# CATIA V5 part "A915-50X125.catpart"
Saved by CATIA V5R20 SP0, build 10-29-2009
Part number: A915-50X125
Source: Unknown
Property "A": "0.000"
Property "ARTICLENO": "A915-50X125"
Property "BOMINFO": "A915-50X125"
Property "CODE": "A915-50X125"
Property "CREATOR": "CADENAS GmbH"
Property "D": "13.500"
Property "D1": "20.000"
Property "FORM": "B"
Property "L": "125.000"
Property "L1": "25.000"
Property "L2": "75.000"
Property "LINA": "A915-50X125"
Property "NB": "A915-50X125"
Property "NBSYN": "$CODE."
Property "NN": "A915"
Property "NT": "VDI 3357 Wear Plates, steel"
Property "SCREW": "M12x25"
Property "SUPPLIER": "CF"
Property "T": "13.000"
Property "W": "50.000"
Bounding box of the stored display mesh (mm): x 0 to 20, y 0 to 125, z -25 to 25
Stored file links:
  C:\Users\borellobunino\Desktop\3D X SITO CF\A915\GSB_OILLESS_G22501050125\A915-50X125.catpart
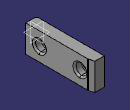
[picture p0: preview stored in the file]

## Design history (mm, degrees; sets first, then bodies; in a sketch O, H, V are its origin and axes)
Body1 "Geometry.1" (main body)
  Solid1 "A915-50X125.catpart": solid without history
